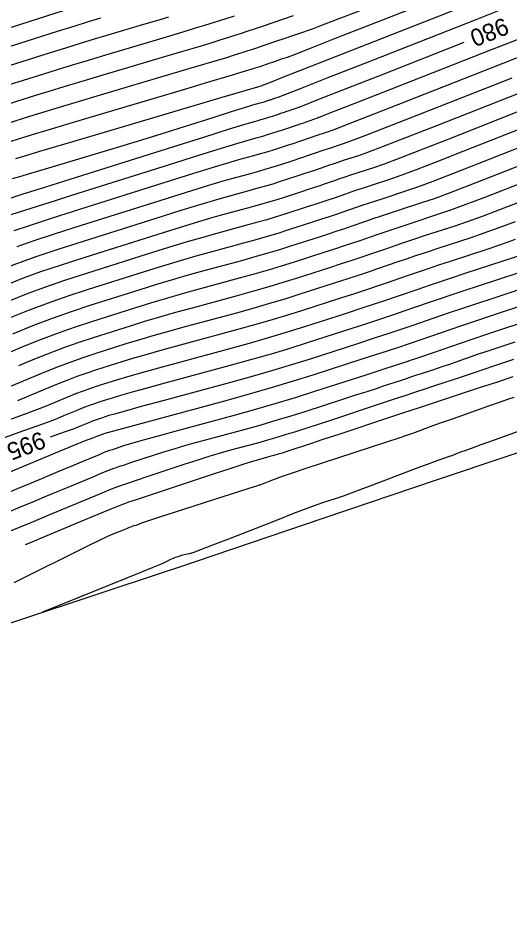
# Model space of a CAD drawing. Extents: x 2175772 to 2185556, y 721391 to 722853.
# Drawn here: x 2178770 to 2178849.6, y 721747 to 721892.9 of the extents above; entities that cross this region are included whole.
import ezdxf

# ---------------------------------------------------------------- set-up
doc = ezdxf.new("R2010")
doc.units = 0
for name, color, linetype in [('DT_X_Contour_Major', 7, 'Continuous'), ('DT_X_Contour_Minor', 7, 'Continuous'), ('DT_X_TIN_Hull', 7, 'Continuous')]:
    doc.layers.add(name, color=color, linetype=linetype)

msp = doc.modelspace()

# ---------------------------------------------------------------- linework, layer by layer
at = {"layer": 'DT_X_Contour_Major'}
for points in [[(2178752.07, 721874.54), (2178754.18, 721875.1), (2178760.25, 721876.67), (2178762.46, 721877.26), (2178764.54, 721877.84), (2178766.5, 721878.41), (2178768.32, 721878.97), (2178773.03, 721880.46), (2178775.03, 721881.08), (2178777.49, 721881.84), (2178780.4, 721882.71), (2178783.78, 721883.72), (2178793.4, 721886.57), (2178796.68, 721887.55), (2178799.3, 721888.33), (2178801.26, 721888.92), (2178802.55, 721889.33), (2178805.13, 721890.15), (2178806.14, 721890.47), (2178807.24, 721890.83), (2178808.43, 721891.23), (2178809.72, 721891.67), (2178814.57, 721893.32)], [(2178768.41, 721863.68), (2178770.65, 721864.39), (2178774.33, 721865.55), (2178779.45, 721867.17), (2178795.04, 721872.08), (2178800.22, 721873.71), (2178804.04, 721874.91), (2178806.52, 721875.68), (2178807.65, 721876.01), (2178808.86, 721876.34), (2178809.3, 721876.47), (2178809.71, 721876.58), (2178810.09, 721876.7), (2178810.44, 721876.81), (2178811.34, 721877.1), (2178811.66, 721877.2), (2178812.18, 721877.37), (2178812.39, 721877.44), (2178812.9, 721877.62), (2178813.1, 721877.69), (2178813.33, 721877.77), (2178813.89, 721877.95), (2178814.71, 721878.22), (2178815.78, 721878.62), (2178818.41, 721879.65), (2178822.58, 721881.28), (2178828.29, 721883.53), (2178842.2, 721889)], [(2178852.9, 721878.52), (2178839.72, 721873.33), (2178835.26, 721871.58), (2178831.77, 721870.23), (2178829.24, 721869.28), (2178827.69, 721868.73), (2178824.82, 721867.8), (2178823.79, 721867.46), (2178822.87, 721867.15), (2178822.05, 721866.88), (2178821.34, 721866.63), (2178819.56, 721866.02), (2178818.83, 721865.77), (2178817.97, 721865.48), (2178816.98, 721865.16), (2178815.87, 721864.8), (2178812.72, 721863.78), (2178811.49, 721863.39), (2178810.15, 721862.99), (2178808.71, 721862.58), (2178807.16, 721862.15), (2178802.9, 721861), (2178801, 721860.46), (2178798.48, 721859.71), (2178795.35, 721858.75), (2178791.6, 721857.58), (2178780.8, 721854.17), (2178776.99, 721852.94), (2178773.66, 721851.82), (2178770.83, 721850.79), (2178768.48, 721849.86)], [(2178851.15, 721863.13), (2178847.94, 721861.89), (2178845.13, 721860.82), (2178842.7, 721859.95), (2178840.67, 721859.25), (2178835.75, 721857.64), (2178833.99, 721857.06), (2178832.41, 721856.54), (2178831, 721856.07), (2178829.77, 721855.64), (2178826.73, 721854.59), (2178825.47, 721854.17), (2178824, 721853.68), (2178822.31, 721853.12), (2178820.39, 721852.5), (2178814.99, 721850.76), (2178812.88, 721850.09), (2178810.59, 721849.4), (2178808.12, 721848.7), (2178805.46, 721847.96), (2178798.16, 721845.98), (2178795.48, 721845.24), (2178792.92, 721844.51), (2178790.48, 721843.79), (2178788.16, 721843.07), (2178782.14, 721841.17), (2178779.86, 721840.42), (2178777.51, 721839.59), (2178775.12, 721838.68), (2178772.66, 721837.69), (2178770.07, 721836.61)], [(2178853.65, 721849.77), (2178846.68, 721847.49), (2178844.19, 721846.67), (2178841.95, 721845.92), (2178839.96, 721845.25), (2178838.21, 721844.66), (2178833.89, 721843.17), (2178832.12, 721842.56), (2178830.03, 721841.87), (2178827.63, 721841.08), (2178824.92, 721840.2), (2178817.27, 721837.73), (2178814.27, 721836.79), (2178811.02, 721835.82), (2178807.52, 721834.81), (2178803.77, 721833.77), (2178793.41, 721830.96), (2178789.95, 721830.02), (2178787.35, 721829.31), (2178785.61, 721828.82), (2178784.72, 721828.57), (2178783.49, 721828.18), (2178783.02, 721828.02), (2178782.54, 721827.85), (2178782.05, 721827.67), (2178781.55, 721827.46), (2178780.19, 721826.9), (2178779.58, 721826.66), (2178778.78, 721826.35), (2178777.77, 721825.98), (2178776.56, 721825.55), (2178775.19, 721825.06)], [(2178850.1, 721834.86), (2178849.11, 721834.52), (2178848.54, 721834.33), (2178847.57, 721834.01), (2178846.21, 721833.56), (2178844.46, 721832.99), (2178839.27, 721831.29), (2178837.2, 721830.61), (2178834.9, 721829.85), (2178832.37, 721829.01), (2178829.61, 721828.1), (2178821.94, 721825.54), (2178819.35, 721824.68), (2178817.32, 721824), (2178815.86, 721823.52), (2178814.97, 721823.23), (2178813.34, 721822.7), (2178812.72, 721822.51), (2178812.08, 721822.31), (2178811.42, 721822.12), (2178810.75, 721821.94), (2178808.91, 721821.44), (2178807.94, 721821.15), (2178806.4, 721820.67), (2178804.28, 721819.98), (2178801.59, 721819.09), (2178793.66, 721816.46), (2178791.04, 721815.58), (2178789.11, 721814.94), (2178787.89, 721814.54), (2178787.37, 721814.37), (2178786.92, 721814.21), (2178786.36, 721813.99), (2178785.03, 721813.45), (2178782.92, 721812.57), (2178780.04, 721811.37), (2178771.32, 721807.74), (2178771.16, 721807.67)]]:
    msp.add_lwpolyline(points, dxfattribs=at)
at = {"layer": 'DT_X_Contour_Minor'}
for points in [[(2178768.02, 721872.73), (2178770.78, 721873.6), (2178772.32, 721874.07), (2178774.86, 721874.84), (2178778.41, 721875.9), (2178782.96, 721877.25), (2178796.44, 721881.25), (2178800.9, 721882.57), (2178804.18, 721883.55), (2178806.28, 721884.18), (2178807.19, 721884.45), (2178808.06, 721884.73), (2178808.4, 721884.84), (2178808.77, 721884.96), (2178809.17, 721885.09), (2178809.6, 721885.24), (2178810.78, 721885.64), (2178811.23, 721885.79), (2178811.66, 721885.94), (2178812.08, 721886.09), (2178812.5, 721886.23), (2178813.6, 721886.6), (2178814.74, 721887.03), (2178817.34, 721888.04), (2178821.4, 721889.63), (2178826.91, 721891.8), (2178843.56, 721898.36)], [(2178769.65, 721870.17), (2178770.96, 721870.57), (2178773.55, 721871.34), (2178777.41, 721872.49), (2178782.55, 721874.02), (2178797.96, 721878.59), (2178803.01, 721880.09), (2178808.79, 721881.8), (2178809.52, 721882.02), (2178809.52, 721882.02), (2178809.53, 721882.02), (2178809.53, 721882.02), (2178809.54, 721882.02), (2178809.55, 721882.03), (2178809.55, 721882.03), (2178809.56, 721882.03), (2178809.56, 721882.03), (2178809.57, 721882.04), (2178810.46, 721882.39), (2178813.13, 721883.43), (2178817.56, 721885.18), (2178823.77, 721887.63), (2178848.92, 721897.53)], [(2178769.13, 721866.92), (2178770.31, 721867.27), (2178772.07, 721867.8), (2178774.42, 721868.5), (2178781.46, 721870.59), (2178784.18, 721871.4), (2178787.03, 721872.27), (2178790.03, 721873.19), (2178793.17, 721874.18), (2178801.72, 721876.87), (2178804.56, 721877.76), (2178806.65, 721878.42), (2178808, 721878.84), (2178808.6, 721879.02), (2178809.2, 721879.18), (2178809.42, 721879.24), (2178809.62, 721879.3), (2178809.81, 721879.36), (2178809.99, 721879.41), (2178810.43, 721879.56), (2178810.59, 721879.61), (2178810.73, 721879.65), (2178810.85, 721879.69), (2178811.21, 721879.82), (2178811.31, 721879.85), (2178811.43, 721879.89), (2178811.56, 721879.93), (2178811.7, 721879.98), (2178812.11, 721880.11), (2178813.09, 721880.49), (2178815.74, 721881.53), (2178820.04, 721883.22), (2178826.01, 721885.57), (2178844.13, 721892.7), (2178850.1, 721895.05)], [(2178768.17, 721875.85), (2178771.91, 721877.03), (2178773.67, 721877.58), (2178776.17, 721878.34), (2178779.41, 721879.31), (2178783.37, 721880.49), (2178794.92, 721883.91), (2178798.79, 721885.06), (2178801.74, 721885.94), (2178803.77, 721886.55), (2178804.87, 721886.89), (2178806.59, 721887.44), (2178807.27, 721887.65), (2178808, 721887.9), (2178808.8, 721888.16), (2178809.66, 721888.45), (2178812.02, 721889.26), (2178812.9, 721889.56), (2178814.61, 721890.14), (2178815.44, 721890.42), (2178817.63, 721891.17), (2178819.02, 721891.68), (2178821.56, 721892.65), (2178825.24, 721894.09)], [(2178768.93, 721891.46), (2178777.54, 721894.19)], [(2178768.48, 721882.1), (2178774.16, 721883.89), (2178776.38, 721884.59), (2178778.8, 721885.33), (2178781.4, 721886.12), (2178784.19, 721886.95), (2178791.89, 721889.23), (2178794.57, 721890.03), (2178796.86, 721890.72), (2178798.74, 721891.3), (2178800.23, 721891.76), (2178803.66, 721892.86), (2178805.01, 721893.29)], [(2178768.63, 721885.22), (2178775.28, 721887.32), (2178777.74, 721888.1), (2178780.11, 721888.83), (2178782.4, 721889.53), (2178784.6, 721890.19), (2178790.37, 721891.9), (2178792.46, 721892.52), (2178794.42, 721893.11)], [(2178768.78, 721888.34), (2178776.41, 721890.76), (2178779.09, 721891.6), (2178781.42, 721892.33), (2178783.4, 721892.93)], [(2178768.89, 721861.1), (2178771.25, 721861.88), (2178774.86, 721863.03), (2178779.72, 721864.57), (2178794.35, 721869.18), (2178799.24, 721870.72), (2178802.93, 721871.87), (2178805.41, 721872.63), (2178806.7, 721873.01), (2178808.52, 721873.51), (2178809.18, 721873.69), (2178809.8, 721873.87), (2178810.37, 721874.04), (2178810.9, 721874.2), (2178812.24, 721874.64), (2178812.72, 721874.79), (2178813.14, 721874.93), (2178813.51, 721875.05), (2178813.82, 721875.16), (2178814.58, 721875.42), (2178814.89, 721875.53), (2178815.24, 721875.64), (2178815.64, 721875.78), (2178816.07, 721875.92), (2178817.3, 721876.32), (2178818.48, 721876.76), (2178821.08, 721877.76), (2178825.12, 721879.34), (2178830.58, 721881.49), (2178847.06, 721887.98), (2178852.48, 721890.11)], [(2178769.38, 721858.53), (2178771.85, 721859.36), (2178775.39, 721860.51), (2178779.99, 721861.97), (2178793.67, 721866.28), (2178798.27, 721867.73), (2178801.82, 721868.83), (2178804.31, 721869.59), (2178805.75, 721870.01), (2178808.18, 721870.67), (2178809.06, 721870.91), (2178809.89, 721871.15), (2178810.65, 721871.38), (2178811.35, 721871.6), (2178813.15, 721872.18), (2178813.79, 721872.38), (2178814.35, 721872.57), (2178814.84, 721872.73), (2178815.26, 721872.87), (2178816.27, 721873.22), (2178816.68, 721873.36), (2178817.15, 721873.52), (2178817.68, 721873.7), (2178818.26, 721873.89), (2178819.9, 721874.42), (2178821.17, 721874.89), (2178823.75, 721875.88), (2178827.65, 721877.4), (2178832.86, 721879.45), (2178848.52, 721885.61), (2178853.67, 721887.64)], [(2178769.86, 721855.95), (2178772.46, 721856.85), (2178775.92, 721857.99), (2178780.26, 721859.37), (2178792.98, 721863.38), (2178797.29, 721864.73), (2178800.7, 721865.79), (2178803.21, 721866.55), (2178804.8, 721867), (2178807.84, 721867.83), (2178808.95, 721868.13), (2178809.97, 721868.43), (2178810.93, 721868.72), (2178811.81, 721868.99), (2178814.05, 721869.72), (2178814.85, 721869.98), (2178815.56, 721870.21), (2178816.17, 721870.41), (2178816.69, 721870.59), (2178817.96, 721871.03), (2178818.47, 721871.2), (2178819.06, 721871.4), (2178819.72, 721871.62), (2178820.45, 721871.86), (2178822.49, 721872.53), (2178823.86, 721873.02), (2178826.43, 721874), (2178830.19, 721875.46), (2178835.15, 721877.41), (2178849.98, 721883.25)], [(2178851.44, 721880.88), (2178837.44, 721875.37), (2178832.72, 721873.52), (2178829.1, 721872.12), (2178826.55, 721871.15), (2178825.09, 721870.63), (2178822.63, 721869.83), (2178821.75, 721869.54), (2178820.96, 721869.28), (2178820.26, 721869.04), (2178819.65, 721868.83), (2178818.12, 721868.3), (2178817.5, 721868.09), (2178816.76, 721867.85), (2178815.92, 721867.57), (2178814.96, 721867.26), (2178812.26, 721866.39), (2178811.21, 721866.05), (2178810.06, 721865.71), (2178808.83, 721865.36), (2178807.5, 721864.99), (2178803.85, 721864), (2178802.1, 721863.5), (2178799.59, 721862.75), (2178796.32, 721861.74), (2178792.29, 721860.48), (2178780.53, 721856.77), (2178776.45, 721855.47), (2178773.06, 721854.33), (2178770.34, 721853.37), (2178768.31, 721852.58)], [(2178854.36, 721876.16), (2178842.01, 721871.29), (2178837.8, 721869.64), (2178834.44, 721868.35), (2178831.94, 721867.42), (2178830.28, 721866.84), (2178827, 721865.76), (2178825.83, 721865.38), (2178824.78, 721865.03), (2178823.84, 721864.71), (2178823.02, 721864.43), (2178820.99, 721863.73), (2178820.16, 721863.45), (2178819.17, 721863.12), (2178818.05, 721862.75), (2178816.77, 721862.34), (2178813.17, 721861.18), (2178811.76, 721860.73), (2178810.24, 721860.28), (2178808.59, 721859.8), (2178806.82, 721859.32), (2178801.95, 721857.99), (2178799.89, 721857.42), (2178797.37, 721856.67), (2178794.37, 721855.76), (2178790.91, 721854.68), (2178781.07, 721851.57), (2178777.52, 721850.42), (2178774.27, 721849.3), (2178771.31, 721848.21), (2178768.65, 721847.15)], [(2178855.82, 721873.79), (2178844.29, 721869.25), (2178840.33, 721867.7), (2178837.11, 721866.47), (2178834.63, 721865.55), (2178832.88, 721864.94), (2178829.19, 721863.73), (2178827.87, 721863.3), (2178826.69, 721862.91), (2178825.63, 721862.55), (2178824.71, 721862.24), (2178822.43, 721861.45), (2178821.49, 721861.13), (2178820.38, 721860.76), (2178819.11, 721860.34), (2178817.68, 721859.88), (2178813.63, 721858.57), (2178812.04, 721858.07), (2178810.32, 721857.56), (2178808.47, 721857.03), (2178806.48, 721856.48), (2178801, 721854.99), (2178798.79, 721854.37), (2178796.25, 721853.63), (2178793.4, 721852.76), (2178790.23, 721851.77), (2178781.33, 721848.97), (2178778.05, 721847.9), (2178774.87, 721846.79), (2178771.79, 721845.63), (2178768.82, 721844.44)], [(2178857.28, 721871.43), (2178846.58, 721867.21), (2178842.87, 721865.76), (2178839.79, 721864.59), (2178837.32, 721863.68), (2178835.47, 721863.04), (2178831.38, 721861.7), (2178829.91, 721861.22), (2178828.59, 721860.78), (2178827.42, 721860.39), (2178826.4, 721860.04), (2178823.86, 721859.16), (2178822.81, 721858.81), (2178821.59, 721858.4), (2178820.18, 721857.94), (2178818.58, 721857.42), (2178814.08, 721855.97), (2178812.32, 721855.41), (2178810.41, 721854.84), (2178808.35, 721854.25), (2178806.14, 721853.64), (2178800.05, 721851.99), (2178797.68, 721851.33), (2178795.14, 721850.59), (2178792.43, 721849.77), (2178789.54, 721848.87), (2178781.6, 721846.37), (2178778.59, 721845.38), (2178775.5, 721844.29), (2178772.34, 721843.08), (2178769.11, 721841.77)], [(2178858.74, 721869.06), (2178848.86, 721865.17), (2178845.41, 721863.83), (2178842.46, 721862.71), (2178840.01, 721861.81), (2178838.07, 721861.15), (2178833.56, 721859.67), (2178831.95, 721859.14), (2178830.5, 721858.66), (2178829.21, 721858.23), (2178828.09, 721857.84), (2178825.29, 721856.88), (2178824.14, 721856.49), (2178822.79, 721856.04), (2178821.24, 721855.53), (2178819.49, 721854.96), (2178814.54, 721853.36), (2178812.6, 721852.75), (2178810.5, 721852.12), (2178808.23, 721851.47), (2178805.8, 721850.8), (2178799.11, 721848.98), (2178796.58, 721848.28), (2178794.03, 721847.55), (2178791.45, 721846.78), (2178788.85, 721845.97), (2178781.87, 721843.77), (2178779.22, 721842.9), (2178776.51, 721841.94), (2178773.73, 721840.88), (2178770.88, 721839.73), (2178763.21, 721836.54)], [(2178850.48, 721859.95), (2178847.8, 721858.94), (2178845.4, 721858.08), (2178843.26, 721857.35), (2178837.93, 721855.61), (2178836.03, 721854.98), (2178834.32, 721854.41), (2178832.79, 721853.9), (2178831.46, 721853.45), (2178828.16, 721852.31), (2178826.8, 721851.85), (2178825.21, 721851.31), (2178823.37, 721850.71), (2178821.3, 721850.04), (2178815.45, 721848.15), (2178813.16, 721847.43), (2178810.67, 721846.69), (2178808, 721845.92), (2178805.12, 721845.12), (2178797.21, 721842.98), (2178794.37, 721842.2), (2178791.8, 721841.47), (2178789.5, 721840.79), (2178787.47, 721840.17), (2178782.41, 721838.58), (2178780.49, 721837.94), (2178778.52, 721837.24), (2178776.5, 721836.48), (2178774.44, 721835.64), (2178768.87, 721833.32)], [(2178850.47, 721857.06), (2178848.09, 721856.21), (2178845.86, 721855.46), (2178840.12, 721853.58), (2178838.07, 721852.9), (2178836.22, 721852.29), (2178834.58, 721851.74), (2178833.15, 721851.25), (2178829.59, 721850.02), (2178828.13, 721849.53), (2178826.41, 721848.95), (2178824.44, 721848.3), (2178822.2, 721847.58), (2178815.9, 721845.55), (2178813.44, 721844.77), (2178810.76, 721843.97), (2178807.88, 721843.14), (2178804.78, 721842.29), (2178796.26, 721839.97), (2178793.27, 721839.15), (2178790.69, 721838.43), (2178788.53, 721837.8), (2178786.78, 721837.27), (2178782.68, 721835.98), (2178781.12, 721835.46), (2178779.52, 721834.9), (2178777.89, 721834.27), (2178776.22, 721833.6), (2178771.7, 721831.72), (2178769.89, 721830.99)], [(2178850.78, 721854.34), (2178848.45, 721853.56), (2178842.31, 721851.55), (2178840.11, 721850.83), (2178838.13, 721850.17), (2178836.37, 721849.58), (2178834.84, 721849.05), (2178831.03, 721847.74), (2178829.46, 721847.2), (2178827.62, 721846.59), (2178825.5, 721845.9), (2178823.11, 721845.12), (2178816.36, 721842.94), (2178813.72, 721842.11), (2178810.85, 721841.25), (2178807.76, 721840.36), (2178804.45, 721839.45), (2178795.31, 721836.97), (2178792.16, 721836.11), (2178789.58, 721835.39), (2178787.56, 721834.81), (2178786.1, 721834.37), (2178782.95, 721833.38), (2178781.75, 721832.98), (2178780.53, 721832.55), (2178779.28, 721832.07), (2178777.99, 721831.55), (2178774.53, 721830.11), (2178772.99, 721829.5), (2178770.97, 721828.73), (2178768.47, 721827.81)], [(2178851.05, 721851.66), (2178844.49, 721849.52), (2178842.15, 721848.75), (2178840.04, 721848.05), (2178838.17, 721847.42), (2178836.52, 721846.86), (2178832.46, 721845.45), (2178830.79, 721844.88), (2178828.82, 721844.23), (2178826.57, 721843.49), (2178824.01, 721842.66), (2178816.81, 721840.34), (2178813.99, 721839.45), (2178810.94, 721838.53), (2178807.64, 721837.59), (2178804.11, 721836.61), (2178794.36, 721833.97), (2178791.06, 721833.07), (2178788.47, 721832.35), (2178786.58, 721831.82), (2178785.41, 721831.47), (2178783.22, 721830.78), (2178782.39, 721830.5), (2178781.54, 721830.2), (2178780.66, 721829.87), (2178779.77, 721829.51), (2178777.36, 721828.51), (2178776.28, 721828.07), (2178774.85, 721827.53), (2178773.06, 721826.88), (2178770.91, 721826.11), (2178764.73, 721823.92)], [(2178856.24, 721847.87), (2178848.86, 721845.45), (2178846.23, 721844.59), (2178843.86, 721843.8), (2178841.75, 721843.09), (2178839.9, 721842.46), (2178835.33, 721840.88), (2178833.45, 721840.24), (2178831.24, 721839.51), (2178828.69, 721838.67), (2178825.82, 721837.74), (2178817.72, 721835.13), (2178814.55, 721834.13), (2178811.11, 721833.1), (2178807.4, 721832.03), (2178803.43, 721830.93), (2178788.85, 721826.98), (2178786.24, 721826.27), (2178784.64, 721825.83), (2178784.03, 721825.66), (2178783.76, 721825.58), (2178783.65, 721825.54), (2178783.55, 721825.51), (2178783.44, 721825.46), (2178783.32, 721825.42), (2178783.02, 721825.29), (2178782.89, 721825.24), (2178782.71, 721825.17), (2178782.48, 721825.09), (2178782.21, 721824.99), (2178781.44, 721824.72), (2178780.71, 721824.43), (2178779.12, 721823.78), (2178776.65, 721822.76), (2178773.32, 721821.38), (2178763.28, 721817.2)], [(2178851.05, 721843.42), (2178848.27, 721842.51), (2178845.79, 721841.69), (2178843.59, 721840.95), (2178841.69, 721840.3), (2178837, 721838.68), (2178835.45, 721838.15), (2178834.33, 721837.76), (2178833.63, 721837.52), (2178833.36, 721837.43), (2178833.21, 721837.38), (2178833.15, 721837.36), (2178833.08, 721837.34), (2178833.01, 721837.31), (2178832.93, 721837.28), (2178832.7, 721837.21), (2178832.24, 721837.06), (2178831.02, 721836.66), (2178829.04, 721836.03), (2178826.3, 721835.14), (2178818, 721832.46), (2178814.83, 721831.46), (2178811.57, 721830.48), (2178808.21, 721829.51), (2178804.75, 721828.55), (2178795.4, 721826.01), (2178792.26, 721825.16), (2178789.85, 721824.49), (2178788.18, 721824.01), (2178787.24, 721823.73), (2178785.72, 721823.22), (2178785.22, 721823.06), (2178784.61, 721822.86), (2178784.51, 721822.82), (2178784.43, 721822.79), (2178784.32, 721822.75), (2178784.06, 721822.65), (2178783.66, 721822.48), (2178783.11, 721822.25), (2178781.43, 721821.55), (2178780.46, 721821.14), (2178778.8, 721820.45), (2178776.44, 721819.47), (2178773.4, 721818.2), (2178764.36, 721814.44)], [(2178850.38, 721840.46), (2178847.97, 721839.66), (2178846.01, 721839), (2178844.49, 721838.49), (2178841.03, 721837.29), (2178839.81, 721836.87), (2178838.74, 721836.51), (2178837.83, 721836.2), (2178837.06, 721835.95), (2178835.23, 721835.35), (2178834.5, 721835.11), (2178833.69, 721834.84), (2178832.8, 721834.55), (2178831.82, 721834.22), (2178829.11, 721833.32), (2178827.94, 721832.93), (2178826.45, 721832.44), (2178824.64, 721831.86), (2178822.52, 721831.17), (2178816.44, 721829.21), (2178814.13, 721828.48), (2178811.74, 721827.76), (2178809.28, 721827.05), (2178806.75, 721826.34), (2178799.91, 721824.49), (2178797.49, 721823.82), (2178795.37, 721823.22), (2178793.55, 721822.67), (2178792.03, 721822.18), (2178788.37, 721820.97), (2178787.16, 721820.57), (2178786.27, 721820.27), (2178785.71, 721820.08), (2178785.47, 721820), (2178785.26, 721819.93), (2178785, 721819.83), (2178784.38, 721819.58), (2178783.41, 721819.18), (2178782.08, 721818.62), (2178778.06, 721816.95), (2178776.45, 721816.27), (2178774.63, 721815.51), (2178772.6, 721814.67), (2178770.36, 721813.74), (2178764.1, 721811.13)], [(2178850.16, 721837.63), (2178848.43, 721837.06), (2178847.29, 721836.67), (2178845.07, 721835.9), (2178844.17, 721835.6), (2178843.16, 721835.26), (2178842.02, 721834.88), (2178840.76, 721834.47), (2178837.25, 721833.32), (2178835.85, 721832.86), (2178834.3, 721832.35), (2178832.59, 721831.78), (2178830.72, 721831.16), (2178825.53, 721829.43), (2178823.64, 721828.8), (2178821.88, 721828.22), (2178820.25, 721827.69), (2178818.74, 721827.2), (2178814.89, 721825.96), (2178813.42, 721825.49), (2178811.91, 721825.04), (2178810.35, 721824.59), (2178808.75, 721824.14), (2178804.41, 721822.96), (2178802.71, 721822.49), (2178800.88, 721821.94), (2178798.91, 721821.32), (2178796.81, 721820.64), (2178791.01, 721818.71), (2178789.1, 721818.07), (2178787.69, 721817.61), (2178786.42, 721817.18), (2178786.09, 721817.07), (2178785.68, 721816.91), (2178784.71, 721816.51), (2178783.17, 721815.88), (2178774.69, 721812.34), (2178772.44, 721811.4), (2178770.46, 721810.58), (2178768.75, 721809.86)], [(2178850.23, 721831.51), (2178849.4, 721831.22), (2178848.05, 721830.74), (2178846.16, 721830.08), (2178840.43, 721828.07), (2178838.49, 721827.38), (2178836.96, 721826.84), (2178835.85, 721826.44), (2178835.14, 721826.18), (2178833.82, 721825.67), (2178833.02, 721825.39), (2178831.62, 721824.92), (2178829.61, 721824.25), (2178827, 721823.4), (2178819.22, 721820.87), (2178816.6, 721820.01), (2178814.54, 721819.33), (2178813.06, 721818.82), (2178812.15, 721818.49), (2178810.48, 721817.84), (2178809.92, 721817.62), (2178809.51, 721817.46), (2178809.25, 721817.37), (2178809.13, 721817.33), (2178809.01, 721817.3), (2178808.6, 721817.18), (2178807.49, 721816.82), (2178805.67, 721816.24), (2178803.14, 721815.42), (2178795.45, 721812.93), (2178792.92, 721812.12), (2178791.1, 721811.52), (2178789.99, 721811.16), (2178789.59, 721811.03), (2178789.48, 721810.97), (2178789.43, 721810.94), (2178789.34, 721810.91), (2178789.21, 721810.87), (2178789.05, 721810.81), (2178788.58, 721810.66), (2178788.35, 721810.58), (2178788.01, 721810.45), (2178787.56, 721810.27), (2178787, 721810.05), (2178785.35, 721809.38), (2178784.48, 721809), (2178783.11, 721808.35), (2178781.23, 721807.43), (2178778.85, 721806.26), (2178771.82, 721802.76), (2178769.3, 721801.53)], [(2178853.45, 721826.93), (2178847.05, 721824.61), (2178844.92, 721823.84), (2178843.33, 721823.27), (2178842.29, 721822.89), (2178841.79, 721822.7), (2178841.19, 721822.47), (2178840.92, 721822.37), (2178840.57, 721822.24), (2178840.13, 721822.08), (2178839.6, 721821.9), (2178838.08, 721821.36), (2178837.32, 721821.09), (2178836.2, 721820.67), (2178834.71, 721820.11), (2178832.85, 721819.4), (2178827.39, 721817.32), (2178825.5, 721816.61), (2178823.91, 721816.02), (2178822.63, 721815.56), (2178821.66, 721815.23), (2178819.46, 721814.51), (2178818.38, 721814.14), (2178816.76, 721813.54), (2178814.6, 721812.71), (2178811.92, 721811.67), (2178804.06, 721808.59), (2178801.46, 721807.58), (2178799.53, 721806.84), (2178798.29, 721806.38), (2178797.72, 721806.2), (2178797.13, 721806.08), (2178796.91, 721806.04), (2178796.67, 721805.98), (2178796.42, 721805.91), (2178796.16, 721805.83), (2178795.46, 721805.6), (2178795.2, 721805.51), (2178794.94, 721805.41), (2178794.7, 721805.3), (2178794.47, 721805.19), (2178793.87, 721804.87), (2178793.66, 721804.77), (2178793.51, 721804.69), (2178793.41, 721804.64), (2178793.36, 721804.62), (2178793.28, 721804.59), (2178792.89, 721804.44), (2178791.79, 721803.99), (2178789.97, 721803.25), (2178787.44, 721802.22), (2178773.94, 721796.74)]]:
    msp.add_lwpolyline(points, dxfattribs=at)
at = {"layer": 'DT_X_TIN_Hull'}
msp.add_lwpolyline([(2178623.73, 721746.95), (2178647.54, 721754.59), (2178648.95, 721755.04), (2178672.7, 721762.83), (2178695.54, 721770.33), (2178719.21, 721778.38), (2178742.87, 721786.43), (2178746.71, 721787.73), (2178770.44, 721795.58), (2178794.18, 721803.43), (2178795.88, 721803.99), (2178819.56, 721812.01), (2178837.71, 721818.16), (2178861.41, 721826.13), (2178885.1, 721834.1), (2178908.8, 721842.07), (2178932.49, 721850.04), (2178956.19, 721858.01), (2178979.88, 721865.98), (2179003.58, 721873.95)], dxfattribs=at)

# ---------------------------------------------------------------- texts
at = {"layer": 'DT_X_Contour_Major'}
for s, rotation, p in [('980', 201.4892, (2178848.69, 721893.06)), ('995', 200.8108, (2178773.76, 721826.09))]:
    msp.add_text(s, height=2.8, rotation=rotation, dxfattribs=at).set_placement(p)

doc.saveas('drawing.dxf')
